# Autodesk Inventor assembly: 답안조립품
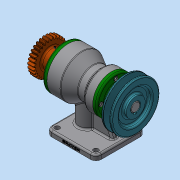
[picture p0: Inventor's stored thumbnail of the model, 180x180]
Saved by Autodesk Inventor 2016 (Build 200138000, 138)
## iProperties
Created: 2019-01
Part Number: 답안조립품
Material: 일반
Document SubType Name: Assembly
Designer: Administrator
Author: Administrator
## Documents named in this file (15)
- C:\Users\Administrator\Desktop\490107V1015\답안조립품.iam
- C:\Users\Administrator\Desktop\490107V1015\본체.ipt
- C:\Users\Administrator\Desktop\490107V1015\축.ipt
- C:\Users\Administrator\Desktop\490107V1015\베어링 6203.ipt
- C:\Users\Administrator\Desktop\490107V1015\키 6 x 6 x 18.ipt
- C:\Users\Administrator\Desktop\490107V1015\키 5 x 5 x 20.ipt
- C:\Users\Administrator\Desktop\490107V1015\뒤커버.ipt
- C:\Users\Administrator\Desktop\490107V1015\볼트 M4.ipt
- C:\Users\Administrator\Desktop\490107V1015\오일 실 17 30 8.ipt
- C:\Users\Administrator\Desktop\490107V1015\V-벨트풀리.ipt
- C:\Users\Administrator\Desktop\490107V1015\멈춤나사 M3.ipt
- C:\Users\Administrator\Desktop\490107V1015\베어링 6205.ipt
- C:\Users\Administrator\Desktop\490107V1015\앞커버.ipt
- C:\Users\Administrator\Desktop\490107V1015\오일 실 25 38 8.ipt
- C:\Users\Administrator\Desktop\490107V1015\스퍼기어.ipt
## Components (1 placed, 1 different names)
1. V-벨트풀리:1
